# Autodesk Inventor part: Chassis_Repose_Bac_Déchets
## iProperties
Created: 2009-02
Part Number: Chassis_Repose_Bac_Déchets
Document SubType Name: Sheet Metal
Designer: claivier
Author: claivier
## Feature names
1. Miroir1 [Mirror]
2. Miroir2 [Mirror]
3. Chanfrein de coin2
4. Perçage2 [Hole]
5. Perçage1 [Hole]
6. Perçage3 [Hole]
7. Perçage4 [Hole]
8. Perçage5 [Hole]
9. Perçage6 [Hole]
10. Plaque1
11. Pli1
12. Plaque2
13. Pli2
14. Plaque3
15. Pli3
16. Couper1
17. Couper2
18. Couper3
